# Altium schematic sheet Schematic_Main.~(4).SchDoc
size A4; SheetNumber: 1; SheetTotal: 1
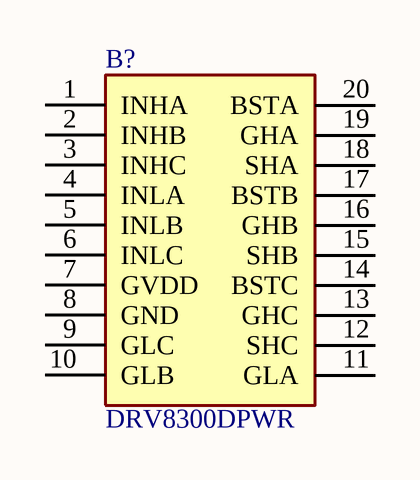
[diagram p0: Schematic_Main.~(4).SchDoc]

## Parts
B?  DRV8300DPWR  [SOP65P640X120-20N]

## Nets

Not connected (* = marked no-connect by the designer): B? 1(INHA) 2(INHB) 3(INHC) 4(INLA) 5(INLB) 6(INLC) 7(GVDD) 8(GND) 9(GLC) 10(GLB) 11(GLA) 12(SHC) 13(GHC) 14(BSTC) 15(SHB) 16(GHB) 17(BSTB) 18(SHA) 19(GHA) 20(BSTA)

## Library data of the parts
B? = DRV8300DPWR: Gate Drivers 100-V max simple 3-phase gate driver with bootstrap diodes 20-TSSOP -40 to 125; Manufacturer_Name: Texas Instruments; Geometry.Height: 1.2mm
